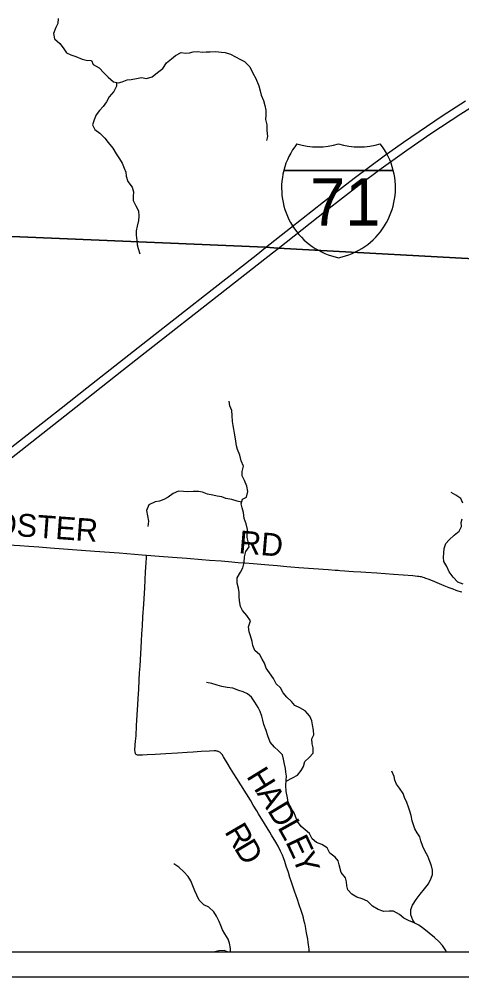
# Model space of a CAD drawing. Extents: x 0 to 34, y 0 to 22.
# Drawn here: x 3.593 to 4.698, y 13.563 to 15.952 of the extents above; entities that cross this region are included whole.
import ezdxf

# ---------------------------------------------------------------- set-up
doc = ezdxf.new("R2010")
doc.units = 0
for name, color, linetype in [('Default', 7, 'Continuous'), ('GM_X_Interstate_Location', 7, 'Continuous'), ('GM_X_Interstate_Route', 7, 'Continuous'), ('GM_X_Interstate_Shield', 7, 'Continuous'), ('GM_X_Minor_River', 7, 'Continuous'), ('GM_X_Township_Road', 7, 'Continuous'), ('GM_X_Township_Road_Text', 7, 'Continuous'), ('SH_Cut_Line', 7, 'Continuous'), ('SH_Data', 7, 'Continuous')]:
    doc.layers.add(name, color=color, linetype=linetype)

msp = doc.modelspace()

# ---------------------------------------------------------------- linework, layer by layer
at = {"layer": 'Default'}
msp.add_lwpolyline([(3.47, 19.2407), (3.2768, 17.1355), (3.2667, 16.919), (3.1974, 16.1596), (3.1343, 15.4291), (3.1796, 15.4266), (4.2078, 15.3826), (4.2393, 15.3805), (4.819, 15.349), (5.5157, 15.319), (7.9465, 15.1727), (8.1234, 15.1688), (8.137, 15.3372), (8.146, 15.4642), (8.2031, 16.209), (8.2895, 16.85), (8.3286, 17.3076), (8.3307, 17.3314), (8.3334, 17.361), (8.3935, 18.0719)], dxfattribs=at)
msp.add_lwpolyline([(2.9696, 13.6252), (8.4279, 13.6252), (8.4024, 15.1386), (8.4023, 15.1576), (8.3761, 15.1587), (8.1234, 15.1688), (7.9465, 15.1727), (5.5157, 15.319), (4.819, 15.349), (4.2393, 15.3805), (4.2078, 15.3826), (3.1796, 15.4266), (3.1343, 15.4291), (3.0617, 14.6751), (3.0457, 14.4958), (3.0429, 14.4692)], close=True, dxfattribs=at)
at = {"layer": 'GM_X_Interstate_Route'}
for points in [[(3.0431, 14.4687), (3.1143, 14.5147), (3.1733, 14.5539), (3.2223, 14.5879), (3.2897, 14.6367), (3.3158, 14.6564), (3.3526, 14.6843), (3.4248, 14.7403), (3.503, 14.8017), (3.7624, 15.0055), (3.8499, 15.0742), (3.9079, 15.1201), (4.0947, 15.2666), (4.2253, 15.3689), (4.2395, 15.3799), (4.3589, 15.4744), (4.4405, 15.5374), (4.4967, 15.5795), (4.5605, 15.6251), (4.6204, 15.6663), (4.6952, 15.7154), (4.7561, 15.754)], [(3.0459, 14.4952), (3.0745, 14.5128), (3.0953, 14.5264), (3.143, 14.5578), (3.1831, 14.5852), (3.2631, 14.6431), (3.2831, 14.658), (3.3199, 14.6854), (3.4098, 14.7551), (3.5176, 14.8402), (3.5637, 14.8759), (3.698, 14.9817), (3.7624, 15.0324), (3.9135, 15.1509), (4.0748, 15.2775), (4.1843, 15.3634), (4.208, 15.3821), (4.2706, 15.4316), (4.3525, 15.4963), (4.4288, 15.5551), (4.5036, 15.6106), (4.5522, 15.6452), (4.6483, 15.7105), (4.7069, 15.7479)]]:
    msp.add_lwpolyline(points, dxfattribs=at)
at = {"layer": 'GM_X_Interstate_Shield'}
for p, q in [((4.2534, 15.5743), (4.5267, 15.5743)), ((4.5267, 15.5743), (4.2534, 15.5743)), ((4.5267, 15.5743), (4.2534, 15.5743))]:
    msp.add_line(p, q, dxfattribs=at)
for centre, start, end in [((4.4256, 15.5308), 141.669, 165.8066), ((4.3382, 15.8107), 253.0091, 286.9909), ((4.4419, 15.8107), 253.0091, 286.9909), ((4.3545, 15.5308), 14.1934, 38.331), ((4.4256, 15.5308), 165.8066, 258.463), ((4.3545, 15.5308), 281.537, 14.1934)]:
    msp.add_arc(centre, 0.1776, start, end, dxfattribs=at)
at = {"layer": 'GM_X_Minor_River'}
for points in [[(3.6909, 15.9535), (3.6895, 15.9407), (3.6851, 15.9309), (3.6791, 15.9158), (3.6815, 15.9025), (3.6945, 15.8909), (3.703, 15.8805), (3.7111, 15.8678), (3.7227, 15.8626), (3.7348, 15.8582), (3.7502, 15.8518), (3.7603, 15.8494), (3.7736, 15.8487), (3.7783, 15.8388), (3.7929, 15.8301), (3.8048, 15.8181), (3.8155, 15.8073), (3.8286, 15.7957), (3.841, 15.7928), (3.8505, 15.7956), (3.8628, 15.8003), (3.8726, 15.8016), (3.8859, 15.8036)], [(3.8859, 15.8036), (3.8989, 15.8064), (3.9113, 15.8035), (3.9251, 15.8082), (3.9385, 15.8189), (3.9516, 15.8289), (3.9606, 15.8424), (3.973, 15.8531), (3.9837, 15.8613), (3.9971, 15.8682), (4.0081, 15.8672), (4.0179, 15.8674), (4.0278, 15.8699), (4.0392, 15.8708), (4.0498, 15.8698), (4.0601, 15.8704), (4.0695, 15.8706), (4.0839, 15.871), (4.0976, 15.8696), (4.1074, 15.8683), (4.1206, 15.8642), (4.1453, 15.8512), (4.1554, 15.8461), (4.1684, 15.8329), (4.176, 15.8169), (4.1841, 15.8038), (4.1909, 15.7855), (4.1948, 15.7732), (4.1973, 15.7618), (4.2027, 15.7492), (4.2066, 15.7362), (4.2086, 15.7248), (4.2087, 15.7123), (4.2081, 15.7013), (4.2109, 15.6879), (4.2114, 15.6739), (4.2126, 15.6591), (4.2105, 15.6493)], [(3.836, 15.7939), (3.8359, 15.7845), (3.8296, 15.7714), (3.8183, 15.7579), (3.8109, 15.7452), (3.8027, 15.734), (3.7938, 15.7239), (3.7856, 15.713), (3.7804, 15.7003), (3.7767, 15.6882), (3.7822, 15.6763), (3.7945, 15.6677), (3.8071, 15.6546), (3.8156, 15.6442), (3.8271, 15.6303), (3.8351, 15.6157), (3.8439, 15.603), (3.8502, 15.5927), (3.8552, 15.5797), (3.8592, 15.5701), (3.8605, 15.5602), (3.8647, 15.5465), (3.8751, 15.5326), (3.879, 15.5208), (3.878, 15.509), (3.8782, 15.4992), (3.8847, 15.4857), (3.8909, 15.4735), (3.8922, 15.4606), (3.8912, 15.4496), (3.8875, 15.4356), (3.8853, 15.4235), (3.8851, 15.4133), (3.8867, 15.4), (3.888, 15.3889), (3.8905, 15.3794), (3.8944, 15.3664)], [(4.2594, 14.051), (4.2749, 14.0595), (4.2875, 14.0657), (4.2969, 14.0773), (4.3028, 14.0878), (4.3061, 14.1002), (4.3165, 14.1103), (4.3266, 14.1211), (4.3268, 14.1343), (4.324, 14.1439), (4.3231, 14.1564), (4.3282, 14.1666), (4.3273, 14.178), (4.3253, 14.1917), (4.3237, 14.2016), (4.3182, 14.2134), (4.3071, 14.2262), (4.2932, 14.2337), (4.2812, 14.2396), (4.2731, 14.2496), (4.2612, 14.2601), (4.252, 14.2713), (4.245, 14.2836), (4.2346, 14.2936), (4.2277, 14.3074), (4.2177, 14.3209), (4.2096, 14.3328), (4.2053, 14.3451), (4.1999, 14.3554), (4.1937, 14.3658), (4.181, 14.3766), (4.1763, 14.3893), (4.175, 14.3995), (4.1704, 14.4137), (4.1668, 14.4236), (4.1652, 14.4358), (4.1708, 14.4505), (4.1616, 14.4639), (4.1504, 14.4763), (4.1454, 14.4866), (4.1434, 14.5007), (4.1425, 14.5113), (4.1423, 14.5216), (4.1406, 14.5322), (4.1371, 14.5445), (4.1374, 14.5585), (4.1456, 14.5724), (4.1515, 14.5829), (4.1548, 14.5965), (4.1558, 14.6105), (4.1591, 14.6237), (4.1673, 14.6357), (4.1656, 14.6452), (4.1625, 14.6589), (4.1624, 14.6692), (4.1626, 14.679), (4.1594, 14.6931), (4.1548, 14.7065), (4.1532, 14.7213), (4.15, 14.7324), (4.1472, 14.7427), (4.1505, 14.754), (4.1608, 14.7595), (4.1641, 14.7734), (4.1614, 14.7872), (4.1556, 14.8009), (4.1498, 14.8128), (4.15, 14.8234), (4.1529, 14.8366), (4.1475, 14.8504), (4.1436, 14.8638), (4.1382, 14.8783), (4.1358, 14.8878), (4.1341, 14.8992), (4.1324, 14.9095), (4.1303, 14.919), (4.1287, 14.9289), (4.1273, 14.9384), (4.1256, 14.948), (4.1248, 14.9632), (4.1235, 14.9753), (4.1192, 14.9872), (4.1172, 14.999)], [(4.1484, 14.7467), (4.1371, 14.7493), (4.1239, 14.7534), (4.1092, 14.7563), (4.0991, 14.7603), (4.0877, 14.7621), (4.0768, 14.7642), (4.0632, 14.7667), (4.0508, 14.7715), (4.0406, 14.7732), (4.0273, 14.7731), (4.0133, 14.773), (4.0035, 14.7736), (3.9906, 14.7742), (3.9772, 14.7688), (3.9653, 14.7592), (3.9546, 14.7537), (3.9435, 14.7494), (3.9325, 14.7473), (3.9168, 14.74), (3.9108, 14.7261), (3.9139, 14.7124), (3.9163, 14.6998), (3.9145, 14.6862)], [(4.7, 14.7446), (4.6949, 14.7561), (4.683, 14.7643), (4.671, 14.771)], [(4.7008, 14.542), (4.6872, 14.5472), (4.6757, 14.56), (4.6662, 14.5727), (4.66, 14.5864), (4.6527, 14.5987), (4.6517, 14.6086), (4.6527, 14.6207), (4.6537, 14.6313), (4.6578, 14.6434), (4.6659, 14.6531), (4.6786, 14.6646), (4.691, 14.6742), (4.6965, 14.6863), (4.6963, 14.6958), (4.6981, 14.7056)], [(4.6029, 13.6823), (4.5902, 13.6916), (4.5767, 13.6984), (4.5662, 13.7027), (4.5531, 13.7094), (4.5419, 13.7184), (4.5269, 13.7263), (4.5163, 13.7269), (4.5026, 13.7256), (4.4887, 13.7308), (4.4749, 13.7395), (4.4626, 13.7515), (4.4491, 13.757), (4.4359, 13.7615), (4.4232, 13.7689), (4.4132, 13.7801), (4.4111, 13.7901), (4.4102, 13.7996), (4.407, 13.8095), (4.3966, 13.8233), (4.3917, 13.8424), (4.3889, 13.852), (4.3815, 13.8616), (4.3681, 13.8713), (4.3615, 13.8848), (4.3484, 13.893), (4.3353, 13.8978), (4.3241, 13.9067), (4.3179, 13.9202), (4.3067, 13.9299), (4.297, 13.9376), (4.2878, 13.9507), (4.2828, 13.9626), (4.2792, 13.9721), (4.2704, 13.9856), (4.2646, 13.999), (4.2615, 14.0131), (4.2591, 14.0253), (4.2582, 14.0397), (4.2596, 14.0533), (4.2602, 14.0632), (4.2589, 14.0731), (4.2576, 14.0826), (4.2551, 14.0933), (4.2524, 14.1059), (4.2499, 14.1169), (4.2396, 14.1277), (4.2299, 14.1359), (4.2195, 14.1482), (4.2138, 14.1643), (4.2095, 14.1777), (4.2041, 14.1926), (4.2013, 14.2029), (4.1989, 14.2128), (4.1949, 14.225), (4.1898, 14.2346), (4.181, 14.248), (4.1729, 14.2603), (4.1633, 14.2689), (4.152, 14.2736), (4.1411, 14.2769), (4.1264, 14.2833), (4.1121, 14.2847), (4.0992, 14.2868), (4.0875, 14.2901), (4.0744, 14.2942), (4.0608, 14.2971)], [(4.5805, 13.6965), (4.5753, 13.7041), (4.5703, 13.7171), (4.5705, 13.7304), (4.5742, 13.7413), (4.5835, 13.7555), (4.5937, 13.769), (4.6045, 13.782), (4.6146, 13.7944), (4.6214, 13.8086), (4.6246, 13.8184), (4.6248, 13.8287), (4.6216, 13.8398), (4.6181, 13.8508), (4.6127, 13.8642), (4.6065, 13.8753), (4.5999, 13.8876), (4.5956, 13.9021), (4.5924, 13.9117), (4.5862, 13.922), (4.5807, 13.9324), (4.5771, 13.942), (4.5739, 13.9523), (4.5708, 13.9652), (4.568, 13.9759), (4.5648, 13.9862), (4.5604, 13.9977), (4.5546, 14.0103), (4.5511, 14.0199), (4.5422, 14.0333), (4.5349, 14.0433), (4.5305, 14.0533), (4.5288, 14.0628), (4.523, 14.0758)], [(4.1206, 13.6252), (4.1204, 13.6334), (4.1184, 13.6467), (4.1148, 13.6567), (4.1063, 13.6697), (4.1005, 13.6797), (4.0961, 13.6908), (4.0926, 13.7007), (4.086, 13.7142), (4.079, 13.7249), (4.0664, 13.7362), (4.054, 13.7425), (4.0421, 13.7537), (4.0363, 13.7664), (4.0312, 13.7771), (4.0269, 13.7901), (4.0219, 13.8027), (4.0153, 13.8135), (4.0038, 13.8251), (3.9919, 13.8367), (3.9796, 13.8449)], [(4.6593, 13.6252), (4.6579, 13.6281), (4.6494, 13.6408), (4.6409, 13.6504), (4.6294, 13.6609), (4.6163, 13.6714), (4.6029, 13.6823)], [(4.1129, 13.6252), (4.1051, 13.6284), (4.0911, 13.6279), (4.0816, 13.6252)]]:
    msp.add_lwpolyline(points, dxfattribs=at)
at = {"layer": 'GM_X_Township_Road'}
for points in [[(3.2114, 14.6618), (3.2267, 14.661), (3.2592, 14.6592), (3.2831, 14.658), (3.3158, 14.6564), (3.3439, 14.655), (3.3645, 14.6539), (3.4244, 14.6507), (3.4535, 14.6491), (3.4777, 14.6478), (3.4971, 14.6466), (3.5191, 14.6449), (3.5413, 14.6431), (3.5496, 14.6424), (3.5658, 14.6411), (3.581, 14.6399), (3.5954, 14.6388), (3.6174, 14.6372), (3.6425, 14.6354), (3.671, 14.6332), (3.7819, 14.6247), (3.8426, 14.6201), (3.9002, 14.6157), (3.9112, 14.6148)], [(4.3171, 13.6252), (4.3171, 13.6255), (4.3168, 13.6309), (4.3162, 13.6373), (4.3155, 13.6425), (4.3146, 13.6483), (4.3131, 13.6567), (4.3105, 13.6722), (4.3085, 13.6829), (4.3073, 13.6889), (4.3058, 13.6958), (4.3037, 13.7045), (4.3023, 13.7104), (4.3008, 13.7154), (4.2975, 13.7261), (4.2921, 13.7423), (4.2876, 13.7556), (4.2836, 13.7672), (4.2812, 13.7742), (4.2762, 13.7887), (4.2726, 13.7993), (4.2687, 13.8109), (4.2649, 13.8227), (4.2595, 13.839), (4.2558, 13.8507), (4.2528, 13.8597), (4.2503, 13.8661), (4.2481, 13.8711), (4.2456, 13.8766), (4.2392, 13.8886), (4.2334, 13.8988), (4.223, 13.9164), (4.2185, 13.9239), (4.2055, 13.9451), (4.1905, 13.9695), (4.1863, 13.9765), (4.1772, 13.9914), (4.1701, 14.0031), (4.1365, 14.0575), (4.1291, 14.0694), (4.1209, 14.0827), (4.1149, 14.0927), (4.1034, 14.1112), (4.0996, 14.1171), (4.0975, 14.1199), (4.0957, 14.1217), (4.0937, 14.1231), (4.0918, 14.1243), (4.09, 14.1251), (4.0882, 14.1257), (4.0861, 14.1261), (4.0843, 14.1262), (4.08, 14.1264), (4.0682, 14.1259), (4.0478, 14.1246), (4.0273, 14.1234), (4.0127, 14.1223), (3.9883, 14.1209), (3.9591, 14.1193), (3.933, 14.1178), (3.9127, 14.1165), (3.9007, 14.1157), (3.8937, 14.1155), (3.8906, 14.1158), (3.8884, 14.1161), (3.887, 14.1165), (3.8856, 14.1173), (3.8847, 14.1181), (3.8839, 14.1192), (3.8833, 14.1207), (3.8827, 14.1227), (3.8824, 14.1243), (3.8823, 14.1272), (3.8831, 14.1413), (3.8839, 14.1507), (3.885, 14.1643), (3.8865, 14.1892), (3.888, 14.2162), (3.8895, 14.2417), (3.8904, 14.2573), (3.8916, 14.2796), (3.8931, 14.3034), (3.894, 14.3215), (3.895, 14.338), (3.8987, 14.4), (3.8998, 14.4186), (3.9008, 14.4387), (3.9022, 14.461), (3.904, 14.4924), (3.9065, 14.5334), (3.9089, 14.573), (3.9102, 14.5958), (3.9109, 14.6089), (3.9112, 14.6148)], [(3.9112, 14.6148), (3.9429, 14.6123), (3.9757, 14.6097), (4.0117, 14.6069), (4.0488, 14.6041), (4.068, 14.6025), (4.0971, 14.6002), (4.1156, 14.5986), (4.1398, 14.5966), (4.156, 14.5953), (4.1769, 14.5936), (4.2058, 14.5912), (4.2369, 14.5887), (4.2607, 14.5867), (4.2914, 14.5843), (4.3645, 14.5787), (4.382, 14.5773), (4.3889, 14.5769), (4.3935, 14.5765), (4.4058, 14.5757), (4.416, 14.575), (4.4272, 14.5743), (4.4459, 14.5731), (4.4584, 14.5722), (4.4852, 14.5703), (4.5274, 14.5674), (4.5512, 14.5656), (4.5751, 14.5638), (4.5867, 14.5627), (4.59, 14.5623), (4.5935, 14.5616), (4.5963, 14.5611), (4.6001, 14.5601), (4.6034, 14.559), (4.6073, 14.5577), (4.6127, 14.5557), (4.6233, 14.5513), (4.6355, 14.5463), (4.6526, 14.5393), (4.6655, 14.5344), (4.6751, 14.5306), (4.6829, 14.5275), (4.6878, 14.5257), (4.6933, 14.524), (4.6976, 14.5228)]]:
    msp.add_lwpolyline(points, dxfattribs=at)
at = {"layer": 'SH_Cut_Line'}
msp.add_lwpolyline([(2.9696, 13.6252), (9.0621, 13.6252), (9.0621, 20.4252), (3.5682, 20.4252), (3.5424, 20.1754), (3.5231, 19.8516), (3.5169, 19.7823), (3.5125, 19.7343), (3.5092, 19.6961), (3.5066, 19.6647), (3.4966, 19.5464), (3.4903, 19.4759), (3.4748, 19.2963), (3.47, 19.2407), (3.2768, 17.1355), (3.2667, 16.919), (3.1974, 16.1596), (3.1343, 15.4291), (3.0617, 14.6751), (3.0457, 14.4958), (3.0429, 14.4692)], close=True, dxfattribs=at)
at = {"layer": 'SH_Data'}
msp.add_line((2.1704, 13.5628), (9.1704, 13.5628), dxfattribs=at)

# ---------------------------------------------------------------- texts
at = {"layer": 'GM_X_Interstate_Location'}
for s in ['-', '.', ',']:
    msp.add_text(s, height=0.000189, dxfattribs=at).set_placement((4.39, 15.4988))
msp.add_text('71', height=0.000189, rotation=0, dxfattribs=at).set_placement((4.3513, 15.4596))
at = {"layer": 'GM_X_Interstate_Shield'}
msp.add_text('71', height=0.11837, dxfattribs=at).set_placement((4.3188, 15.4367))
at = {"layer": 'GM_X_Township_Road_Text'}
for s, height, rotation, p in [('DOSTER', 0.05682, 355.8161, (3.472, 14.6707)), ('RD', 0.05682, 355.1585, (4.1398, 14.6198)), ('H', 0.0568, 301.5644, (4.1589, 14.0632)), ('A', 0.0568, 301.566, (4.185, 14.0206)), ('D', 0.0568, 301.1427, (4.2112, 13.9781)), ('L', 0.0568, 299.2186, (4.2368, 13.9358)), ('R', 0.0568, 300.2295, (4.1044, 13.9251)), ('D', 0.0568, 300.6376, (4.1282, 13.8844)), ('E', 0.0568, 295.3173, (4.257, 13.8996)), ('Y', 0.0568, 289.3024, (4.2746, 13.8626))]:
    msp.add_text(s, height=height, rotation=rotation, dxfattribs=at).set_placement(p)

doc.saveas('drawing.dxf')
